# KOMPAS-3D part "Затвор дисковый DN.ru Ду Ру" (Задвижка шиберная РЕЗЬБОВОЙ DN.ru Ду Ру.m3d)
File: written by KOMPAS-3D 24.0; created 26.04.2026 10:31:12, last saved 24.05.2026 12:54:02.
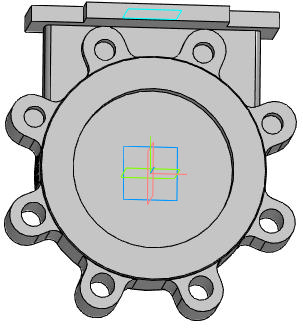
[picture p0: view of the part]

Document properties: Автор: R2D2; Полное имя файла: E:\Работа\Зайцев\GVKR1331M-1W-Fb-2P Задвижка шиберная с выдвижным штоком DN.ru Ду50-300 Ру16-10-6 с пневмоприводом\исходные материалы\DN150\Задвижка шиберная РЕЗЬБОВОЙ DN.ru Ду Ру.m3d

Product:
- Part/product: Затвор дисковый DN.ru Ду Ру
    Масса: 18.2
    Раздел спецификации: Прочие изделия
    Примечание: D050-23732

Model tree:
1. Смещенная плоскость:2
2. Диск
3. Корпус
4. Элемент выдавливания:3
     Расстояние 1 = 30
5. Элемент вращения:1
     Угол 1 = 360
6. Корпус штока
7. Элемент выдавливания:6  (with: Грань.Элемент вращения:1)
     Расстояние 1 = 150
8. Ушко  (with: Ребро.Элемент вращения:1)
9. Элемент выдавливания:5
10. Эскиз:1  (with: Ребро.Элемент выдавливания:5)
11. Элемент выдавливания:12
     Расстояние 1 = 28.5; Расстояние 2 = 28.5
12. Элемент выдавливания:13
13. Массив по концентрической сетке:1  (with: Элемент выдавливания:13, Эскиз:1, Элемент выдавливания:12, Элемент выдавливания:5, Грань.Элемент вращения:1)  (8 pattern instances)
     Шаг 2 = 360
14. Эскиз:2  (labels: Ребро.Элемент выдавливания:5.Экземпляр ( 1, 6 ); Ребро.Элемент выдавливания:5.Экземпляр ( 1, 5 ); Ребро.Элемент выдавливания:5.Экземпляр ( 1, 4 ); Ребро.Элемент выдавливания:5.Экземпляр ( 1, 7 ))
15. Элемент выдавливания:14
16. площадка  (with: Грань.Элемент выдавливания:6, Ребро.Элемент выдавливания:5)
17. Элемент выдавливания:15
     Расстояние 2 = 15
18. Скругление:10  (with: Ребро.Элемент выдавливания:6)
     Радиус = 5
19. Эскиз:4  (labels: Задвижка шиберная с выдвижным штоком DN.ru Ду50 Ру16; Затвор дисковый DN.ru Ду200 Ру16)
20. Элемент выдавливания:16  (with: Грань.Элемент вращения:1)
     Расстояние 1 = 106.5; Смещение 1 = 1
21. Эскиз:5  (labels: Задвижка шиберная DN.ru Ду50 Ру10; Затвор дисковый DN.ru Ду200 Ру16)
22. Элемент выдавливания:17  (with: Грань.Элемент вращения:1)
     Расстояние 1 = 106.497; Смещение 1 = 1
23. Скругление:8  (with: Ребро.Элемент вращения:1)
     Радиус = 1
24. Скругление:11  (with: Ребро.Элемент выдавливания:16)
     Радиус = 10

Expressions: 360/n; c-8-2*t; v1301/2; d/2+30; dd/2
Referenced files in E:\Работа\Зайцев\GVKR1331E-1W-Fb-2P Задвижка шиберная DN.ru Ду50-300 Ру16-10-6\исходные материалы\DN50\: GVKR1331E-1W-Fb-2P Задвижка шиберная с выдвижным штоком DN.ru Ду50 Ру16.a3d, GVKR1331E-1W-Fb-2P Задвижка шиберная DN.ru Ду50 Ру16.a3d
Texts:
  Угловой размер с обрывом
  GOST 26.020 Pr3
  var3D
  ширина затвора по металлу
  площадка под крепеж
  DN+10
  dk+20
  dk-10
  Плоскость ZY.Начало координат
